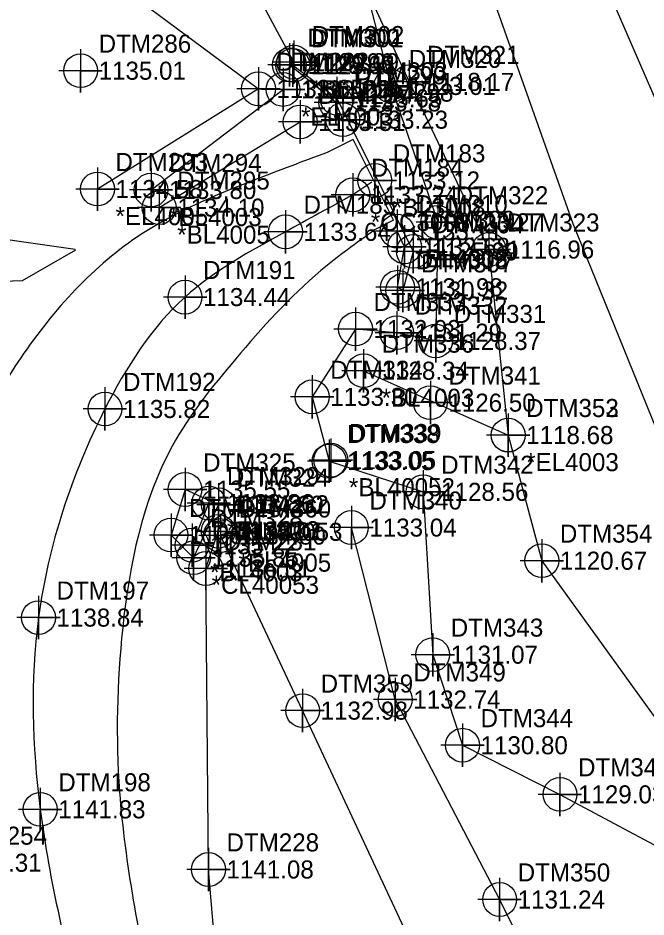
# Model space of a CAD drawing. Extents: x 1286409 to 1286829, y 857931 to 858308.
# Drawn here: x 1286511.7 to 1286598.7, y 858032.3 to 858156.8 of the extents above; entities that cross this region are included whole.
import ezdxf

# ---------------------------------------------------------------- set-up
doc = ezdxf.new("R2010")
doc.units = 0
for name, color, linetype in [('Exist DTM Breakline', 7, 'Continuous'), ('Exist DTM Breakline Cogo Comment', 7, 'Continuous'), ('Exist DTM Breakline Cogo Elevation', 7, 'Continuous'), ('Exist DTM Breakline Cogo Number', 7, 'Continuous'), ('Exist DTM Breakline Cogo Point CELL', 7, 'Continuous'), ('Exist DTM Breakline Underwater', 7, 'Continuous'), ('Exist DTM Crownline', 7, 'Continuous'), ('Exist DTM Crownline Cogo Comment', 7, 'Continuous'), ('Exist DTM Crownline Cogo Elevation', 7, 'Continuous'), ('Exist DTM Crownline Cogo Number', 7, 'Continuous'), ('Exist DTM Crownline Cogo Point CELL', 7, 'Continuous'), ('Exist DTM Drainline', 7, 'Continuous'), ('Exist DTM Drainline Cogo Comment', 7, 'Continuous'), ('Exist DTM Drainline Cogo Elevation', 7, 'Continuous'), ('Exist DTM Drainline Cogo Number', 7, 'Continuous'), ('Exist DTM Drainline Cogo Point CELL', 7, 'Continuous'), ('Exist DTM Regular Point CELL', 7, 'Continuous'), ('Exist DTM Regular Point Cogo Elevation', 7, 'Continuous'), ('Exist DTM Regular Point Cogo Number', 7, 'Continuous'), ('Exist Hydro Stream or Body of Water', 7, 'Continuous'), ('Exist Roads EOP', 7, 'Continuous'), ('Exist Roads EOP Other', 7, 'Continuous')]:
    doc.layers.add(name, color=color, linetype=linetype)

msp = doc.modelspace()

# ---------------------------------------------------------------- linework, layer by layer
at = {"layer": 'Exist DTM Breakline'}
for points in [[(1286536.003, 858236.961), (1286552.055, 858201.893), (1286559.903, 858160.92), (1286565.827, 858147.987), (1286576.897, 858124.766), (1286579.562, 858099.067), (1286584.222, 858081.673), (1286607.668, 858049.163), (1286601.672, 858086.174)], [(1286530.298, 858233.7), (1286543.261, 858195.881), (1286559.854, 858160.955), (1286563.292, 858147.427), (1286569.804, 858128.536), (1286569.528, 858112.107), (1286564.126, 858113.252), (1286558.412, 858113.755), (1286552.418, 858104.363), (1286554.757, 858095.462), (1286567.776, 858091.209), (1286569.105, 858068.653), (1286573.239, 858056.109), (1286586.738, 858049.307), (1286601.784, 858041.235), (1286607.702, 858042.424), (1286614.823, 858014.95)], [(1286549.858, 858150.722), (1286538.911, 858171.077), (1286534.01, 858197.304), (1286522.897, 858229.418)], [(1286503.403, 858220.596), (1286517.153, 858179.744), (1286523.583, 858162.909), (1286544.969, 858147.024), (1286522.671, 858133.149)], [(1286531.22, 858130.575), (1286550.75, 858142.443), (1286556.647, 858142.752), (1286555.671, 858145.149), (1286549.259, 858150.349), (1286549.734, 858150.284), (1286555.847, 858145.711), (1286566.418, 858124.511), (1286564.969, 858119.097), (1286564.239, 858119.544), (1286565.212, 858125.138), (1286564.186, 858127.313)], [(1286539.421, 858089.424), (1286534.805, 858091.523), (1286532.858, 858085.228), (1286535.988, 858082.083), (1286539.421, 858089.424)], [(1286544.306, 857959.455), (1286542.498, 857991.356), (1286539.471, 858022.109), (1286538.051, 858038.904), (1286537.678, 858080.597), (1286539.403, 858085.731)], [(1286563.919, 858062.445), (1286557.838, 858086.259)], [(1286581.943, 857992.271), (1286566.826, 858027.199), (1286551.086, 858060.906), (1286539.718, 858085.149)], [(1286563.919, 858062.445), (1286578.38, 858034.745), (1286593.083, 858004.927)]]:
    msp.add_lwpolyline(points, dxfattribs=at)
at = {"layer": 'Exist DTM Breakline Cogo Point CELL'}
for points in [[(1286549.259, 858153.349), (1286549.259, 858147.349), (1286549.259, 858150.349), (1286552.259, 858150.349), (1286546.259, 858150.349)], [(1286549.734, 858153.284), (1286549.734, 858147.284), (1286549.734, 858150.284), (1286552.734, 858150.284), (1286546.734, 858150.284)], [(1286549.858, 858153.722), (1286549.858, 858147.722), (1286549.858, 858150.722), (1286552.858, 858150.722), (1286546.858, 858150.722)], [(1286563.292, 858150.427), (1286563.292, 858144.427), (1286563.292, 858147.427), (1286566.292, 858147.427), (1286560.292, 858147.427)], [(1286565.827, 858150.987), (1286565.827, 858144.987), (1286565.827, 858147.987), (1286568.827, 858147.987), (1286562.827, 858147.987)], [(1286544.969, 858150.024), (1286544.969, 858144.024), (1286544.969, 858147.024), (1286547.969, 858147.024), (1286541.969, 858147.024)], [(1286555.671, 858148.149), (1286555.671, 858142.149), (1286555.671, 858145.149), (1286558.671, 858145.149), (1286552.671, 858145.149)], [(1286555.847, 858148.711), (1286555.847, 858142.711), (1286555.847, 858145.711), (1286558.847, 858145.711), (1286552.847, 858145.711)], [(1286550.75, 858145.443), (1286550.75, 858139.443), (1286550.75, 858142.443), (1286553.75, 858142.443), (1286547.75, 858142.443)], [(1286556.647, 858145.752), (1286556.647, 858139.752), (1286556.647, 858142.752), (1286559.647, 858142.752), (1286553.647, 858142.752)], [(1286522.671, 858136.149), (1286522.671, 858130.149), (1286522.671, 858133.149), (1286525.671, 858133.149), (1286519.671, 858133.149)], [(1286531.22, 858133.575), (1286531.22, 858127.575), (1286531.22, 858130.575), (1286534.22, 858130.575), (1286528.22, 858130.575)], [(1286569.804, 858131.536), (1286569.804, 858125.536), (1286569.804, 858128.536), (1286572.804, 858128.536), (1286566.804, 858128.536)], [(1286564.186, 858130.313), (1286564.186, 858124.313), (1286564.186, 858127.313), (1286567.186, 858127.313), (1286561.186, 858127.313)], [(1286565.212, 858128.138), (1286565.212, 858122.138), (1286565.212, 858125.138), (1286568.212, 858125.138), (1286562.212, 858125.138)], [(1286566.418, 858127.511), (1286566.418, 858121.511), (1286566.418, 858124.511), (1286569.418, 858124.511), (1286563.418, 858124.511)], [(1286576.897, 858127.766), (1286576.897, 858121.766), (1286576.897, 858124.766), (1286579.897, 858124.766), (1286573.897, 858124.766)], [(1286564.239, 858122.544), (1286564.239, 858116.544), (1286564.239, 858119.544), (1286567.239, 858119.544), (1286561.239, 858119.544)], [(1286564.969, 858122.097), (1286564.969, 858116.097), (1286564.969, 858119.097), (1286567.969, 858119.097), (1286561.969, 858119.097)], [(1286558.412, 858116.755), (1286558.412, 858110.755), (1286558.412, 858113.755), (1286561.412, 858113.755), (1286555.412, 858113.755)], [(1286564.126, 858116.252), (1286564.126, 858110.252), (1286564.126, 858113.252), (1286567.126, 858113.252), (1286561.126, 858113.252)], [(1286569.528, 858115.107), (1286569.528, 858109.107), (1286569.528, 858112.107), (1286572.528, 858112.107), (1286566.528, 858112.107)], [(1286552.418, 858107.363), (1286552.418, 858101.363), (1286552.418, 858104.363), (1286555.418, 858104.363), (1286549.418, 858104.363)], [(1286568.782, 858106.563), (1286568.782, 858100.563), (1286568.782, 858103.563), (1286571.782, 858103.563), (1286565.782, 858103.563)], [(1286579.562, 858102.067), (1286579.562, 858096.067), (1286579.562, 858099.067), (1286582.562, 858099.067), (1286576.562, 858099.067)], [(1286554.757, 858098.462), (1286554.757, 858092.462), (1286554.757, 858095.462), (1286557.757, 858095.462), (1286551.757, 858095.462)], [(1286555.001, 858098.602), (1286555.001, 858092.602), (1286555.001, 858095.602), (1286558.001, 858095.602), (1286552.001, 858095.602)], [(1286534.805, 858094.523), (1286534.805, 858088.523), (1286534.805, 858091.523), (1286537.805, 858091.523), (1286531.805, 858091.523)], [(1286567.776, 858094.209), (1286567.776, 858088.209), (1286567.776, 858091.209), (1286570.776, 858091.209), (1286564.776, 858091.209)], [(1286539.421, 858092.424), (1286539.421, 858086.424), (1286539.421, 858089.424), (1286542.421, 858089.424), (1286536.421, 858089.424)], [(1286532.858, 858088.228), (1286532.858, 858082.228), (1286532.858, 858085.228), (1286535.858, 858085.228), (1286529.858, 858085.228)], [(1286539.403, 858088.731), (1286539.403, 858082.731), (1286539.403, 858085.731), (1286542.403, 858085.731), (1286536.403, 858085.731)], [(1286539.718, 858088.149), (1286539.718, 858082.149), (1286539.718, 858085.149), (1286542.718, 858085.149), (1286536.718, 858085.149)], [(1286557.838, 858089.259), (1286557.838, 858083.259), (1286557.838, 858086.259), (1286560.838, 858086.259), (1286554.838, 858086.259)], [(1286535.988, 858085.083), (1286535.988, 858079.083), (1286535.988, 858082.083), (1286538.988, 858082.083), (1286532.988, 858082.083)], [(1286584.222, 858084.673), (1286584.222, 858078.673), (1286584.222, 858081.673), (1286587.222, 858081.673), (1286581.222, 858081.673)], [(1286537.678, 858083.597), (1286537.678, 858077.597), (1286537.678, 858080.597), (1286540.678, 858080.597), (1286534.678, 858080.597)], [(1286569.105, 858071.653), (1286569.105, 858065.653), (1286569.105, 858068.653), (1286572.105, 858068.653), (1286566.105, 858068.653)], [(1286563.919, 858065.445), (1286563.919, 858059.445), (1286563.919, 858062.445), (1286566.919, 858062.445), (1286560.919, 858062.445)], [(1286551.086, 858063.906), (1286551.086, 858057.906), (1286551.086, 858060.906), (1286554.086, 858060.906), (1286548.086, 858060.906)], [(1286573.239, 858059.109), (1286573.239, 858053.109), (1286573.239, 858056.109), (1286576.239, 858056.109), (1286570.239, 858056.109)], [(1286586.738, 858052.307), (1286586.738, 858046.307), (1286586.738, 858049.307), (1286589.738, 858049.307), (1286583.738, 858049.307)], [(1286538.051, 858041.904), (1286538.051, 858035.904), (1286538.051, 858038.904), (1286541.051, 858038.904), (1286535.051, 858038.904)], [(1286578.38, 858037.745), (1286578.38, 858031.745), (1286578.38, 858034.745), (1286581.38, 858034.745), (1286575.38, 858034.745)]]:
    msp.add_lwpolyline(points, dxfattribs=at)
for centre in [(1286549.858, 858150.722), (1286549.259, 858150.349), (1286549.734, 858150.284), (1286565.827, 858147.987), (1286544.969, 858147.024), (1286563.292, 858147.427), (1286555.847, 858145.711), (1286555.671, 858145.149), (1286550.75, 858142.443), (1286556.647, 858142.752), (1286522.671, 858133.149), (1286531.22, 858130.575), (1286569.804, 858128.536), (1286564.186, 858127.313), (1286565.212, 858125.138), (1286566.418, 858124.511), (1286576.897, 858124.766), (1286564.239, 858119.544), (1286564.969, 858119.097), (1286558.412, 858113.755), (1286564.126, 858113.252), (1286569.528, 858112.107), (1286552.418, 858104.363), (1286568.782, 858103.563), (1286579.562, 858099.067), (1286554.757, 858095.462), (1286555.001, 858095.602), (1286534.805, 858091.523), (1286567.776, 858091.209), (1286539.421, 858089.424), (1286539.403, 858085.731), (1286557.838, 858086.259), (1286532.858, 858085.228), (1286539.718, 858085.149), (1286535.988, 858082.083), (1286584.222, 858081.673), (1286537.678, 858080.597), (1286569.105, 858068.653), (1286563.919, 858062.445), (1286551.086, 858060.906), (1286573.239, 858056.109), (1286586.738, 858049.307), (1286538.051, 858038.904), (1286578.38, 858034.745)]:
    msp.add_circle(centre, 2.344, dxfattribs=at)
at = {"layer": 'Exist DTM Breakline Underwater'}
msp.add_lwpolyline([(1286646.614, 858037.087), (1286629.153, 858089.196), (1286603.619, 858137.215), (1286590.426, 858167.626), (1286563.88, 858237.106), (1286548.712, 858281.174)], dxfattribs=at)
at = {"layer": 'Exist DTM Crownline'}
msp.add_line((1286560.697, 858134.088), (1286558.043, 858132.348), dxfattribs=at)
msp.add_spline([(1286558.043, 858132.348), (1286548.721, 858127.222), (1286534.801, 858118.181), (1286523.71, 858102.686), (1286514.506, 858073.789), (1286514.745, 858047.233), (1286520.815, 858017.78), (1286528.017, 857987.278), (1286533.078, 857960.044)], degree=3, dxfattribs=at)
at = {"layer": 'Exist DTM Crownline Cogo Point CELL'}
for points in [[(1286561.08, 858137.339), (1286561.08, 858131.339), (1286561.08, 858134.339), (1286564.08, 858134.339), (1286558.08, 858134.339)], [(1286558.043, 858135.348), (1286558.043, 858129.348), (1286558.043, 858132.348), (1286561.043, 858132.348), (1286555.043, 858132.348)], [(1286548.721, 858130.222), (1286548.721, 858124.222), (1286548.721, 858127.222), (1286551.721, 858127.222), (1286545.721, 858127.222)], [(1286534.801, 858121.181), (1286534.801, 858115.181), (1286534.801, 858118.181), (1286537.801, 858118.181), (1286531.801, 858118.181)], [(1286523.71, 858105.686), (1286523.71, 858099.686), (1286523.71, 858102.686), (1286526.71, 858102.686), (1286520.71, 858102.686)], [(1286514.506, 858076.789), (1286514.506, 858070.789), (1286514.506, 858073.789), (1286517.506, 858073.789), (1286511.506, 858073.789)], [(1286514.745, 858050.233), (1286514.745, 858044.233), (1286514.745, 858047.233), (1286517.745, 858047.233), (1286511.745, 858047.233)]]:
    msp.add_lwpolyline(points, dxfattribs=at)
for centre in [(1286561.08, 858134.339), (1286558.043, 858132.348), (1286548.721, 858127.222), (1286534.801, 858118.181), (1286523.71, 858102.686), (1286514.506, 858073.789), (1286514.745, 858047.233)]:
    msp.add_circle(centre, 2.344, dxfattribs=at)
at = {"layer": 'Exist DTM Drainline'}
for p, q in [((1286530.088, 858133.018), (1286548.374, 858146.946)), ((1286559.536, 858107.986), (1286579.556, 858099.072)), ((1286535.774, 858083.813), (1286538.102, 858089.643))]:
    msp.add_line(p, q, dxfattribs=at)
at = {"layer": 'Exist DTM Drainline Cogo Point CELL'}
for points in [[(1286548.374, 858149.946), (1286548.374, 858143.946), (1286548.374, 858146.946), (1286551.374, 858146.946), (1286545.374, 858146.946)], [(1286530.088, 858136.018), (1286530.088, 858130.018), (1286530.088, 858133.018), (1286533.088, 858133.018), (1286527.088, 858133.018)], [(1286559.536, 858110.986), (1286559.536, 858104.986), (1286559.536, 858107.986), (1286562.536, 858107.986), (1286556.536, 858107.986)], [(1286579.556, 858102.072), (1286579.556, 858096.072), (1286579.556, 858099.072), (1286582.556, 858099.072), (1286576.556, 858099.072)], [(1286538.102, 858092.643), (1286538.102, 858086.643), (1286538.102, 858089.643), (1286541.102, 858089.643), (1286535.102, 858089.643)], [(1286535.774, 858086.813), (1286535.774, 858080.813), (1286535.774, 858083.813), (1286538.774, 858083.813), (1286532.774, 858083.813)]]:
    msp.add_lwpolyline(points, dxfattribs=at)
for centre in [(1286548.374, 858146.946), (1286530.088, 858133.018), (1286559.536, 858107.986), (1286579.556, 858099.072), (1286538.102, 858089.643), (1286535.774, 858083.813)]:
    msp.add_circle(centre, 2.344, dxfattribs=at)
at = {"layer": 'Exist DTM Regular Point CELL'}
msp.add_lwpolyline([(1286520.339, 858152.536), (1286520.339, 858146.536), (1286520.339, 858149.536), (1286523.339, 858149.536), (1286517.339, 858149.536)], dxfattribs=at)
msp.add_circle((1286520.339, 858149.536), 2.344, dxfattribs=at)
at = {"layer": 'Exist Hydro Stream or Body of Water'}
msp.add_lwpolyline([(1286633.369, 858010.272), (1286619.226, 858059.374), (1286604.574, 858088.843), (1286588.568, 858128.319), (1286577.591, 858159.308), (1286547.36, 858229.805), (1286531.042, 858265.146)], dxfattribs=at)
at = {"layer": 'Exist Roads EOP'}
for p, q in [((1286558.102, 858140.011), (1286554.506, 858138.221)), ((1286563.674, 858128.817), (1286561.061, 858127.479))]:
    msp.add_line(p, q, dxfattribs=at)
msp.add_lwpolyline([(1286563.674, 858128.817), (1286558.102, 858140.011)], dxfattribs=at)
for points in [[(1286554.506, 858138.221), (1286544.419, 858134.401), (1286528.832, 858126.933), (1286512.047, 858109.768), (1286502.652, 858089.088), (1286501.393, 858072.897), (1286505.471, 858045.649), (1286512.056, 858016.522), (1286519.805, 857984.681), (1286525.58, 857958.7)], [(1286561.061, 858127.479), (1286553.633, 858121.854), (1286541.776, 858109.576), (1286533.023, 858097.553), (1286526.163, 858072.381), (1286525.732, 858049.679), (1286530.491, 858019.74), (1286536.523, 857989.722), (1286542.222, 857961.323)]]:
    msp.add_spline(points, degree=3, dxfattribs=at)
at = {"layer": 'Exist Roads EOP Other'}
for points in [[(1286457.489, 858144.476), (1286471.264, 858136.623), (1286492.557, 858128.739), (1286511.821, 858125.921), (1286519.606, 858124.807)], [(1286453.703, 858139.674), (1286466.954, 858129.445), (1286491.774, 858119.764), (1286512.279, 858120.499), (1286519.676, 858124.715)]]:
    msp.add_lwpolyline(points, dxfattribs=at)

# ---------------------------------------------------------------- texts
at = {"layer": 'Exist DTM Breakline Cogo Comment'}
for s, p in [('*BL40051', (1286552.358, 858145.722)), ('*EL4005', (1286525.171, 858128.149)), ('*BL4005', (1286533.72, 858125.575)), ('*EL4005', (1286566.686, 858122.313)), ('*BL40052', (1286557.501, 858090.602)), ('*BL40053', (1286541.921, 858084.424)), ('*EL4005', (1286542.218, 858080.149)), ('*CL40053', (1286538.488, 858077.083))]:
    msp.add_text(s, height=2.5, dxfattribs=at).set_placement(p)
at = {"layer": 'Exist DTM Breakline Cogo Elevation'}
for s, p in [('1129.63', (1286551.759, 858149.099)), ('1129.11', (1286552.234, 858149.034)), ('1129.09', (1286552.358, 858149.472)), ('1118.17', (1286568.327, 858146.737)), ('1133.65', (1286547.469, 858145.774)), ('1123.01', (1286565.792, 858146.177)), ('1125.65', (1286558.347, 858144.461)), ('1133.18', (1286558.171, 858143.899)), ('1133.31', (1286553.25, 858141.193)), ('1133.23', (1286559.147, 858141.502)), ('1134.58', (1286525.171, 858131.899)), ('1134.10', (1286533.72, 858129.325)), ('1123.27', (1286572.304, 858127.286)), ('1133.11', (1286566.686, 858126.063)), ('1132.68', (1286567.712, 858123.888)), ('1125.99', (1286568.918, 858123.261)), ('1116.96', (1286579.397, 858123.516)), ('1131.98', (1286566.739, 858118.294)), ('1130.32', (1286567.469, 858117.847)), ('1132.93', (1286560.912, 858112.505)), ('1131.29', (1286566.626, 858112.002)), ('1128.37', (1286572.028, 858110.857)), ('1133.30', (1286554.918, 858103.113)), ('1126.50', (1286571.282, 858102.313)), ('1118.68', (1286582.062, 858097.817)), ('1133.05', (1286557.501, 858094.352)), ('1133.05', (1286557.257, 858094.212)), ('1135.55', (1286537.305, 858090.273)), ('1128.56', (1286570.276, 858089.959)), ('1134.60', (1286541.921, 858088.174)), ('1135.01', (1286541.903, 858084.481)), ('1133.04', (1286560.338, 858085.009)), ('1136.11', (1286535.358, 858083.978)), ('1134.80', (1286542.218, 858083.899)), ('1135.85', (1286538.488, 858080.833)), ('1136.31', (1286540.178, 858079.347)), ('1120.67', (1286586.722, 858080.423)), ('1131.07', (1286571.605, 858067.403)), ('1132.74', (1286566.419, 858061.195)), ('1132.98', (1286553.586, 858059.656)), ('1130.80', (1286575.739, 858054.859)), ('1129.03', (1286589.238, 858048.057)), ('1142.31', (1286502.857, 858038.584)), ('1141.08', (1286540.551, 858037.654)), ('1131.24', (1286580.88, 858033.495))]:
    msp.add_text(s, height=2.5, dxfattribs=at).set_placement(p)
at = {"layer": 'Exist DTM Breakline Cogo Number'}
for s, p in [('DTM300', (1286551.759, 858152.849)), ('DTM301', (1286552.234, 858152.784)), ('DTM302', (1286552.358, 858153.222)), ('DTM321', (1286568.327, 858150.487)), ('DTM292', (1286547.469, 858149.524)), ('DTM320', (1286565.792, 858149.927)), ('DTM303', (1286558.347, 858148.211)), ('DTM299', (1286558.171, 858147.649)), ('DTM297', (1286553.25, 858144.943)), ('DTM298', (1286559.147, 858145.252)), ('DTM293', (1286525.171, 858135.649)), ('DTM295', (1286533.72, 858133.075)), ('DTM322', (1286572.304, 858131.036)), ('DTM310', (1286566.686, 858129.813)), ('DTM309', (1286567.712, 858127.638)), ('DTM304', (1286568.918, 858127.011)), ('DTM323', (1286579.397, 858127.266)), ('DTM308', (1286566.739, 858122.044)), ('DTM307', (1286567.469, 858121.597)), ('DTM333', (1286560.912, 858116.255)), ('DTM332', (1286566.626, 858115.752)), ('DTM331', (1286572.028, 858114.607)), ('DTM334', (1286554.918, 858106.863)), ('DTM341', (1286571.282, 858106.063)), ('DTM353', (1286582.062, 858101.567)), ('DTM339', (1286557.501, 858098.102)), ('DTM338', (1286557.257, 858097.962)), ('DTM325', (1286537.305, 858094.023)), ('DTM342', (1286570.276, 858093.709)), ('DTM324', (1286541.921, 858091.924)), ('DTM232', (1286541.903, 858088.231)), ('DTM340', (1286560.338, 858088.759)), ('DTM326', (1286535.358, 858087.728)), ('DTM360', (1286542.218, 858087.649)), ('DTM327', (1286538.488, 858084.583)), ('DTM231', (1286540.178, 858083.097)), ('DTM354', (1286586.722, 858084.173)), ('DTM343', (1286571.605, 858071.153)), ('DTM349', (1286566.419, 858064.945)), ('DTM359', (1286553.586, 858063.406)), ('DTM344', (1286575.739, 858058.609)), ('DTM345', (1286589.238, 858051.807)), ('DTM254', (1286502.857, 858042.334)), ('DTM228', (1286540.551, 858041.404)), ('DTM350', (1286580.88, 858037.245))]:
    msp.add_text(s, height=2.5, dxfattribs=at).set_placement(p)
at = {"layer": 'Exist DTM Crownline Cogo Comment'}
for s, p in [('*BL3008', (1286563.58, 858129.339)), ('*OC3008', (1286560.543, 858127.348))]:
    msp.add_text(s, height=2.5, dxfattribs=at).set_placement(p)
at = {"layer": 'Exist DTM Crownline Cogo Elevation'}
for s, p in [('1133.12', (1286563.58, 858133.089)), ('1133.24', (1286560.543, 858131.098)), ('1133.64', (1286551.221, 858125.972)), ('1134.44', (1286537.301, 858116.931)), ('1135.82', (1286526.21, 858101.436)), ('1138.84', (1286517.006, 858072.539)), ('1141.83', (1286517.245, 858045.983))]:
    msp.add_text(s, height=2.5, dxfattribs=at).set_placement(p)
at = {"layer": 'Exist DTM Crownline Cogo Number'}
for s, p in [('DTM183', (1286563.58, 858136.839)), ('DTM184', (1286560.543, 858134.848)), ('DTM185', (1286551.221, 858129.722)), ('DTM191', (1286537.301, 858120.681)), ('DTM192', (1286526.21, 858105.186)), ('DTM197', (1286517.006, 858076.289)), ('DTM198', (1286517.245, 858049.733))]:
    msp.add_text(s, height=2.5, dxfattribs=at).set_placement(p)
at = {"layer": 'Exist DTM Drainline Cogo Comment'}
for s, p in [('*EL4003', (1286550.874, 858141.946)), ('*BL4003', (1286532.588, 858128.018)), ('*BL4003', (1286562.036, 858102.986)), ('*EL4003', (1286582.056, 858094.072)), ('*EL4003', (1286540.602, 858084.643)), ('*BL4003', (1286538.274, 858078.813))]:
    msp.add_text(s, height=2.5, dxfattribs=at).set_placement(p)
at = {"layer": 'Exist DTM Drainline Cogo Elevation'}
for s, p in [('1132.22', (1286550.874, 858145.696)), ('1133.80', (1286532.588, 858131.768)), ('1128.34', (1286562.036, 858106.736)), ('1118.68', (1286582.056, 858097.822)), ('1132.86', (1286540.602, 858088.393)), ('1135.22', (1286538.274, 858082.563))]:
    msp.add_text(s, height=2.5, dxfattribs=at).set_placement(p)
at = {"layer": 'Exist DTM Drainline Cogo Number'}
for s, p in [('DTM296', (1286550.874, 858149.446)), ('DTM294', (1286532.588, 858135.518)), ('DTM336', (1286562.036, 858110.486)), ('DTM352', (1286582.056, 858101.572)), ('DTM329', (1286540.602, 858092.143)), ('DTM328', (1286538.274, 858086.313))]:
    msp.add_text(s, height=2.5, dxfattribs=at).set_placement(p)
at = {"layer": 'Exist DTM Regular Point Cogo Elevation'}
msp.add_text('1135.01', height=2.5, dxfattribs=at).set_placement((1286522.839, 858148.286))
at = {"layer": 'Exist DTM Regular Point Cogo Number'}
msp.add_text('DTM286', height=2.5, dxfattribs=at).set_placement((1286522.839, 858152.036))

doc.saveas('drawing.dxf')
